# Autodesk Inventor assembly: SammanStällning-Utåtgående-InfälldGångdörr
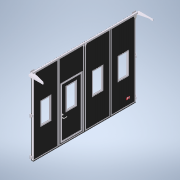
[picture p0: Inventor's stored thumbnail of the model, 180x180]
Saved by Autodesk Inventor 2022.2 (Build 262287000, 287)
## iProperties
Created: 2022-02
Part Number: SammanStällning-Utåtgående-InfälldGångdörr
Document SubType Name: Assembly
Designer: cl
Author: cl
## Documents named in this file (20)
- G:\AutoCad\Carl Lund\3D-modeller systemlösningar\3D-modell-systemlösning-2022\SammanStällning-Utåtgående-InfälldGångdörr.iam
- G:\AutoCad\Carl Lund\3D-modeller systemlösningar\3D-modell-systemlösning-2022\Parts\BladKomplett2022.iam
- G:\AutoCad\Carl Lund\3D-modeller systemlösningar\3D-modell-systemlösning-2022\Parts\MellanGångjärnH.ipt
- G:\AutoCad\Carl Lund\3D-modeller systemlösningar\3D-modell-systemlösning-2022\Parts\MellanGångjärnV.ipt
- G:\AutoCad\Carl Lund\3D-modeller systemlösningar\3D-modell-systemlösning-2022\Parts\Karmstyrning.ipt
- G:\AutoCad\Carl Lund\3D-modeller systemlösningar\3D-modell-systemlösning-2022\Parts\KarmgångjärnH.ipt
- G:\AutoCad\Carl Lund\3D-modeller systemlösningar\3D-modell-systemlösning-2022\Parts\KarmgångjärnV.ipt
- G:\AutoCad\Carl Lund\3D-modeller systemlösningar\3D-modell-systemlösning-2022\Parts\SidotätningUppe.ipt
- G:\AutoCad\Carl Lund\3D-modeller systemlösningar\3D-modell-systemlösning-2022\Parts\SidoTätning.ipt
- G:\AutoCad\Carl Lund\3D-modeller systemlösningar\3D-modell-systemlösning-2022\Parts\SläpList.ipt
- G:\AutoCad\Carl Lund\3D-modeller systemlösningar\3D-modell-systemlösning-2022\Parts\GummilistMellan.ipt
- G:\AutoCad\Carl Lund\3D-modeller systemlösningar\3D-modell-systemlösning-2022\Styrande.iam
- G:\AutoCad\Carl Lund\3D-modeller systemlösningar\3D-modell-systemlösning-2022\Parts\GarageregelHöger.ipt
- G:\AutoCad\Carl Lund\3D-modeller systemlösningar\3D-modell-systemlösning-2022\Parts\GarageregelVänster.ipt
- G:\AutoCad\Carl Lund\3D-modeller systemlösningar\3D-modell-systemlösning-2022\Parts\styrrulle.ipt
- G:\AutoCad\Carl Lund\3D-modeller systemlösningar\3D-modell-systemlösning-2022\Parts\Styrskena.ipt
- G:\AutoCad\Carl Lund\3D-modeller systemlösningar\3D-modell-systemlösning-2022\Parts\Uppställningsbeslag-H-Ut.ipt
- G:\AutoCad\Carl Lund\3D-modeller systemlösningar\3D-modell-systemlösning-2022\Parts\Uppställningsbeslag-V-Ut.ipt
- G:\AutoCad\Carl Lund\3D-modeller systemlösningar\3D-modell-systemlösning-2022\Parts\BladKomplettInfälld2022.iam
- G:\AutoCad\Carl Lund\3D-modeller systemlösningar\3D-modell-systemlösning-2022\Parts\Logga.ipt
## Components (50 placed, 18 different names)
1. Logga:1 — Mate:202, Mate:203, Mate:204
2. BladKomplett2022:1 [sub-assembly] — Mate:1, Mate:2, Flush:1, Flush:2, Flush:3, Flush:8, Flush:28, Flush:29, Mate:28, Flush:30, Mate:42, Mate:39, Flush:99, Flush:100, Flush:101, Flush:102, Flush:103, Flush:104, Mate:61, Mate:66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
3. BladKomplett2022:2 [sub-assembly] — Flush:2, Flush:3, Flush:8, Mate:65, Flush:148, Flush:149, Flush:171, Flush:177, Flush:178, Mate:182, Flush:181, Flush:184, Mate:196, Flush:215
4. BladKomplett2022:3 [sub-assembly] — Flush:30, Flush:101, Flush:102, Mate:183, Flush:185, Flush:186, Flush:189, Flush:192
5. BladKomplett2022:4 [sub-assembly] — Flush:32, Flush:100, Flush:103, Mate:64, Flush:146, Flush:147, Mate:184, Flush:193, Flush:194, Flush:197
6. BladKomplett2022:5 [sub-assembly] — Flush:31, Flush:99, Flush:104, Mate:63, Flush:144, Flush:145, Mate:81, Flush:168, Flush:200, Mate:185, Flush:201, Flush:202, Flush:205, Flush:208, Flush:219
7. BladKomplettInfälld2022:1 [sub-assembly] — Flush:220, Flush:221, Flush:222, Mate:198, Flush:223, Flush:224, Flush:227, Flush:230, Flush:231, Flush:232, Mate:200, Flush:233, Mate:201, Flush:234
8. BladKomplett2022:6 [sub-assembly] — Mate:28, Flush:28, Flush:29, Flush:31, Flush:32, Mate:38, Flush:138, Flush:139, Mate:58, Mate:62, Flush:142, Flush:143, Mate:69, Mate:78, Flush:159, Flush:160, Mate:180, Mate:186, Mate:187, Mate:192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
9. GarageregelHöger:1 — Flush:156, Flush:157, Flush:158
10. GarageregelHöger:2 — Mate:77, Flush:154, Flush:155, Flush:156, Flush:157, Flush:158
11. GarageregelVänster:1 — Flush:161, Flush:162, Flush:163
12. GarageregelVänster:2 — Mate:78, Flush:159, Flush:160, Flush:161, Flush:162, Flush:163
13. Karmstyrning:2 — Mate:38, Flush:138, Mate:186, Flush:209
14. Karmstyrning:3 — Mate:39, Mate:189, Flush:210
15. Karmstyrning:4 — Mate:42, Mate:61, Mate:188, Flush:209
16. KarmgångjärnH:1 — Mate:190, Mate:191, Flush:211, Flush:213, Flush:214
17. KarmgångjärnV:1 — Mate:192, Flush:212, Mate:193, Flush:217, Flush:218
18. Karmstyrning:1 — Flush:139, Mate:58, Mate:187, Flush:210
19. MellanGångjärnH:7 — Flush:177, Flush:178, Mate:182, Flush:179, Flush:180
20. MellanGångjärnH:8 — Flush:179, Flush:180, Flush:181, Flush:182, Flush:183
21. MellanGångjärnH:9 — Flush:182, Flush:183, Flush:184
22. MellanGångjärnV:7 — Mate:183, Flush:185, Flush:186, Flush:187, Flush:188
23. MellanGångjärnV:8 — Flush:187, Flush:188, Flush:189, Flush:190, Flush:191
24. MellanGångjärnV:9 — Flush:190, Flush:191, Flush:192
25. MellanGångjärnH:10 — Flush:198, Flush:199, Flush:200
26. MellanGångjärnH:11 — Flush:195, Flush:196, Flush:197, Flush:198, Flush:199
27. MellanGångjärnH:12 — Mate:184, Flush:193, Flush:194, Flush:195, Flush:196
28. MellanGångjärnV:10 — Mate:185, Flush:201, Flush:202, Flush:203, Flush:204
29. MellanGångjärnV:11 — Flush:203, Flush:204, Flush:205, Flush:206, Flush:207
30. MellanGångjärnV:12 — Flush:206, Flush:207, Flush:208
31. MellanGångjärnH:13 — Flush:225, Flush:226, Flush:227, Flush:228, Flush:229
32. MellanGångjärnH:14 — Flush:228, Flush:229, Flush:230
33. MellanGångjärnH:15 — Mate:198, Flush:223, Flush:224, Flush:225, Flush:226
34. GummilistMellan:6 — Flush:233, Mate:201, Flush:234
35. GummilistMellan:2 — Mate:63, Flush:144, Flush:145
36. GummilistMellan:3 — Mate:64, Flush:146, Flush:147
37. GummilistMellan:4 — Mate:65, Flush:148, Flush:149
38. GummilistMellan:5 — Mate:66, Flush:150, Flush:151
39. SidotätningUppe:1 — Mate:68, Mate:178, Flush:176, Mate:179, Mate:181
40. SidoTätning:1 — Mate:69, Mate:76, Mate:180, Mate:181
41. SidoTätning:2 — Mate:72, Mate:177, Mate:179
42. SläpList:1 — Mate:75, Flush:153, Mate:76
43. GummilistMellan:1 — Mate:62, Flush:142, Flush:143
44. styrrulle:3 — Flush:231, Flush:232, Mate:200
45. Uppställningsbeslag-H-Ut:1 — Flush:213, Flush:214, Mate:194, Mate:195, Flush:216, Mate:199
46. Uppställningsbeslag-V-Ut:1 — Flush:217, Mate:197, Flush:218
47. styrrulle:1 — Mate:81, Flush:168, Flush:219
48. styrrulle:2 — Flush:171, Mate:196, Flush:215
49. Styrskena:1 — Flush:174, Mate:176, Flush:175, Mate:195, Flush:216, Mate:199
50. Styrskena:2 — Flush:174, Mate:176, Flush:175
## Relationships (151: Flush 101, Mate 50)
- Mate:1: BladKomplett2022:1
- Mate:2: BladKomplett2022:1
- Flush:1: BladKomplett2022:1
- Flush:2: BladKomplett2022:1 ↔ BladKomplett2022:2
- Flush:3: BladKomplett2022:1 ↔ BladKomplett2022:2
- Flush:8: BladKomplett2022:1 ↔ BladKomplett2022:2
- Mate:28: BladKomplett2022:1 ↔ BladKomplett2022:6
- Flush:28: BladKomplett2022:1 ↔ BladKomplett2022:6
- Flush:29: BladKomplett2022:1 ↔ BladKomplett2022:6
- Flush:30: BladKomplett2022:1 ↔ BladKomplett2022:3
- Flush:31: BladKomplett2022:5 ↔ BladKomplett2022:6
- Flush:32: BladKomplett2022:4 ↔ BladKomplett2022:6
- Mate:38: BladKomplett2022:6 ↔ Karmstyrning:2
- Mate:39: BladKomplett2022:1 ↔ Karmstyrning:3
- Mate:42: BladKomplett2022:1 ↔ Karmstyrning:4
- Flush:99: BladKomplett2022:1 ↔ BladKomplett2022:5
- Flush:100: BladKomplett2022:1 ↔ BladKomplett2022:4
- Flush:101: BladKomplett2022:1 ↔ BladKomplett2022:3
- Flush:102: BladKomplett2022:1 ↔ BladKomplett2022:3
- Flush:103: BladKomplett2022:1 ↔ BladKomplett2022:4
- Flush:104: BladKomplett2022:1 ↔ BladKomplett2022:5
- Flush:138: BladKomplett2022:6 ↔ Karmstyrning:2
- Flush:139: BladKomplett2022:6 ↔ Karmstyrning:1
- Mate:58: BladKomplett2022:6 ↔ Karmstyrning:1
- Mate:61: BladKomplett2022:1 ↔ Karmstyrning:4
- Mate:62: BladKomplett2022:6 ↔ GummilistMellan:1
- Flush:142: BladKomplett2022:6 ↔ GummilistMellan:1
- Flush:143: BladKomplett2022:6 ↔ GummilistMellan:1
- Mate:63: BladKomplett2022:5 ↔ GummilistMellan:2
- Flush:144: BladKomplett2022:5 ↔ GummilistMellan:2
- Flush:145: BladKomplett2022:5 ↔ GummilistMellan:2
- Mate:64: BladKomplett2022:4 ↔ GummilistMellan:3
- Flush:146: BladKomplett2022:4 ↔ GummilistMellan:3
- Flush:147: BladKomplett2022:4 ↔ GummilistMellan:3
- Mate:65: BladKomplett2022:2 ↔ GummilistMellan:4
- Flush:148: BladKomplett2022:2 ↔ GummilistMellan:4
- Flush:149: BladKomplett2022:2 ↔ GummilistMellan:4
- Mate:66: BladKomplett2022:1 ↔ GummilistMellan:5
- Flush:150: BladKomplett2022:1 ↔ GummilistMellan:5
- Flush:151: BladKomplett2022:1 ↔ GummilistMellan:5
- Mate:68: BladKomplett2022:1 ↔ SidotätningUppe:1
- Mate:69: BladKomplett2022:6 ↔ SidoTätning:1
- Mate:72: BladKomplett2022:1 ↔ SidoTätning:2
- Mate:75: BladKomplett2022:1 ↔ SläpList:1
- Flush:153: BladKomplett2022:1 ↔ SläpList:1
- Mate:76: SidoTätning:1 ↔ SläpList:1
- Mate:77: BladKomplett2022:1 ↔ GarageregelHöger:2
- Flush:154: BladKomplett2022:1 ↔ GarageregelHöger:2
- Flush:155: BladKomplett2022:1 ↔ GarageregelHöger:2
- Flush:156: GarageregelHöger:1 ↔ GarageregelHöger:2
- Flush:157: GarageregelHöger:1 ↔ GarageregelHöger:2
- Flush:158: GarageregelHöger:1 ↔ GarageregelHöger:2
- Mate:78: BladKomplett2022:6 ↔ GarageregelVänster:2
- Flush:159: BladKomplett2022:6 ↔ GarageregelVänster:2
- Flush:160: BladKomplett2022:6 ↔ GarageregelVänster:2
- Flush:161: GarageregelVänster:1 ↔ GarageregelVänster:2
- Flush:162: GarageregelVänster:1 ↔ GarageregelVänster:2
- Flush:163: GarageregelVänster:1 ↔ GarageregelVänster:2
- Mate:81: BladKomplett2022:5 ↔ styrrulle:1
- Flush:168: BladKomplett2022:5 ↔ styrrulle:1
- Flush:171: BladKomplett2022:2 ↔ styrrulle:2
- Flush:174: Styrskena:1 ↔ Styrskena:2
- Mate:176: Styrskena:1 ↔ Styrskena:2
- Flush:175: Styrskena:1 ↔ Styrskena:2
- Mate:177: BladKomplett2022:1 ↔ SidoTätning:2
- Mate:178: BladKomplett2022:1 ↔ SidotätningUppe:1
- Flush:176: BladKomplett2022:1 ↔ SidotätningUppe:1
- Mate:179: SidotätningUppe:1 ↔ SidoTätning:2
- Mate:180: BladKomplett2022:6 ↔ SidoTätning:1
- Mate:181: SidotätningUppe:1 ↔ SidoTätning:1
- Flush:177: BladKomplett2022:2 ↔ MellanGångjärnH:7
- Flush:178: BladKomplett2022:2 ↔ MellanGångjärnH:7
- Mate:182: BladKomplett2022:2 ↔ MellanGångjärnH:7
- Flush:179: MellanGångjärnH:7 ↔ MellanGångjärnH:8
- Flush:180: MellanGångjärnH:7 ↔ MellanGångjärnH:8
- Flush:181: BladKomplett2022:2 ↔ MellanGångjärnH:8
- Flush:182: MellanGångjärnH:8 ↔ MellanGångjärnH:9
- Flush:183: MellanGångjärnH:8 ↔ MellanGångjärnH:9
- Flush:184: BladKomplett2022:2 ↔ MellanGångjärnH:9
- Mate:183: BladKomplett2022:3 ↔ MellanGångjärnV:7
- Flush:185: BladKomplett2022:3 ↔ MellanGångjärnV:7
- Flush:186: BladKomplett2022:3 ↔ MellanGångjärnV:7
- Flush:187: MellanGångjärnV:7 ↔ MellanGångjärnV:8
- Flush:188: MellanGångjärnV:7 ↔ MellanGångjärnV:8
- Flush:189: BladKomplett2022:3 ↔ MellanGångjärnV:8
- Flush:190: MellanGångjärnV:8 ↔ MellanGångjärnV:9
- Flush:191: MellanGångjärnV:8 ↔ MellanGångjärnV:9
- Flush:192: BladKomplett2022:3 ↔ MellanGångjärnV:9
- Mate:184: BladKomplett2022:4 ↔ MellanGångjärnH:12
- Flush:193: BladKomplett2022:4 ↔ MellanGångjärnH:12
- Flush:194: BladKomplett2022:4 ↔ MellanGångjärnH:12
- Flush:195: MellanGångjärnH:11 ↔ MellanGångjärnH:12
- Flush:196: MellanGångjärnH:11 ↔ MellanGångjärnH:12
- Flush:197: BladKomplett2022:4 ↔ MellanGångjärnH:11
- Flush:198: MellanGångjärnH:10 ↔ MellanGångjärnH:11
- Flush:199: MellanGångjärnH:10 ↔ MellanGångjärnH:11
- Flush:200: BladKomplett2022:5 ↔ MellanGångjärnH:10
- Mate:185: BladKomplett2022:5 ↔ MellanGångjärnV:10
- Flush:201: BladKomplett2022:5 ↔ MellanGångjärnV:10
- Flush:202: BladKomplett2022:5 ↔ MellanGångjärnV:10
- Flush:203: MellanGångjärnV:10 ↔ MellanGångjärnV:11
- Flush:204: MellanGångjärnV:10 ↔ MellanGångjärnV:11
- Flush:205: BladKomplett2022:5 ↔ MellanGångjärnV:11
- Flush:206: MellanGångjärnV:11 ↔ MellanGångjärnV:12
- Flush:207: MellanGångjärnV:11 ↔ MellanGångjärnV:12
- Flush:208: BladKomplett2022:5 ↔ MellanGångjärnV:12
- Mate:186: BladKomplett2022:6 ↔ Karmstyrning:2
- Mate:187: BladKomplett2022:6 ↔ Karmstyrning:1
- Mate:188: BladKomplett2022:1 ↔ Karmstyrning:4
- Flush:209: Karmstyrning:2 ↔ Karmstyrning:4
- Mate:189: BladKomplett2022:1 ↔ Karmstyrning:3
- Flush:210: Karmstyrning:3 ↔ Karmstyrning:1
- Mate:190: BladKomplett2022:1 ↔ KarmgångjärnH:1
- Mate:191: BladKomplett2022:1 ↔ KarmgångjärnH:1
- Flush:211: BladKomplett2022:1 ↔ KarmgångjärnH:1
- Mate:192: BladKomplett2022:6 ↔ KarmgångjärnV:1
- Flush:212: BladKomplett2022:6 ↔ KarmgångjärnV:1
- Mate:193: BladKomplett2022:6 ↔ KarmgångjärnV:1
- Flush:213: KarmgångjärnH:1 ↔ Uppställningsbeslag-H-Ut:1
- Flush:214: KarmgångjärnH:1 ↔ Uppställningsbeslag-H-Ut:1
- Mate:194: BladKomplett2022:1 ↔ Uppställningsbeslag-H-Ut:1
- Mate:195: Uppställningsbeslag-H-Ut:1 ↔ Styrskena:1
- Mate:196: BladKomplett2022:2 ↔ styrrulle:2
- Flush:215: BladKomplett2022:2 ↔ styrrulle:2
- Flush:216: Uppställningsbeslag-H-Ut:1 ↔ Styrskena:1
- Flush:217: KarmgångjärnV:1 ↔ Uppställningsbeslag-V-Ut:1
- Mate:197: BladKomplett2022:6 ↔ Uppställningsbeslag-V-Ut:1
- Flush:218: KarmgångjärnV:1 ↔ Uppställningsbeslag-V-Ut:1
- Flush:219: BladKomplett2022:5 ↔ styrrulle:1
- Flush:220: BladKomplett2022:1 ↔ BladKomplettInfälld2022:1
- Flush:221: BladKomplett2022:1 ↔ BladKomplettInfälld2022:1
- Flush:222: BladKomplett2022:1 ↔ BladKomplettInfälld2022:1
- Mate:198: BladKomplettInfälld2022:1 ↔ MellanGångjärnH:15
- Flush:223: BladKomplettInfälld2022:1 ↔ MellanGångjärnH:15
- Flush:224: BladKomplettInfälld2022:1 ↔ MellanGångjärnH:15
- Flush:225: MellanGångjärnH:13 ↔ MellanGångjärnH:15
- Flush:226: MellanGångjärnH:13 ↔ MellanGångjärnH:15
- Flush:227: BladKomplettInfälld2022:1 ↔ MellanGångjärnH:13
- Flush:228: MellanGångjärnH:13 ↔ MellanGångjärnH:14
- Flush:229: MellanGångjärnH:13 ↔ MellanGångjärnH:14
- Flush:230: BladKomplettInfälld2022:1 ↔ MellanGångjärnH:14
- Mate:199: Uppställningsbeslag-H-Ut:1 ↔ Styrskena:1
- Flush:231: BladKomplettInfälld2022:1 ↔ styrrulle:3
- Flush:232: BladKomplettInfälld2022:1 ↔ styrrulle:3
- Mate:200: BladKomplettInfälld2022:1 ↔ styrrulle:3
- Flush:233: BladKomplettInfälld2022:1 ↔ GummilistMellan:6
- Mate:201: BladKomplettInfälld2022:1 ↔ GummilistMellan:6
- Flush:234: BladKomplettInfälld2022:1 ↔ GummilistMellan:6
- Mate:202: Logga:1 ↔ BladKomplett2022:6
- Mate:203: Logga:1 ↔ BladKomplett2022:6
- Mate:204: Logga:1 ↔ BladKomplett2022:6
## Named parameters: Blad2 = 0, Blad3 = 0, Blad4 = 0, Blad5 = 1012.5 mm, MGJ12Djup = 48 mm, MGJ56Djup = 0, MGJ56Bredd = 0, MGJ23Djup = 48 mm, MGJ45Djup = 48 mm, GarageRegel5 = 0, GarageRegel6 = 0, BladBredd = 987.5 mm, Fönsterhöjd = 862 mm, Blad2_1 = 0, Blad3_1 = 0, Blad4_1 = 0, Blad5_1 = 1012.5 mm, Blad6 = 2025 mm, MGJ12Djup_1 = 48 mm, MGJ2Djup = 0, MGJ2Bredd = 5012.5 mm, MGJ56Djup_1 = 0, MGJ56Bredd_1 = 0, MGJ23Djup_1 = 48 mm, MGJ45Djup_1 = 48 mm, GarageRegel5_1 = 0, GarageRegel6_1 = 0, Styrrulle2Djup = 0, FönsterhöjdStyrning = 862 mm, FönsterKarm = 54 mm, AndraGlasraden = 0, BrösthöjdStyrning2 = 0.0001 mm, Infälldstyr = 1012.5 mm
